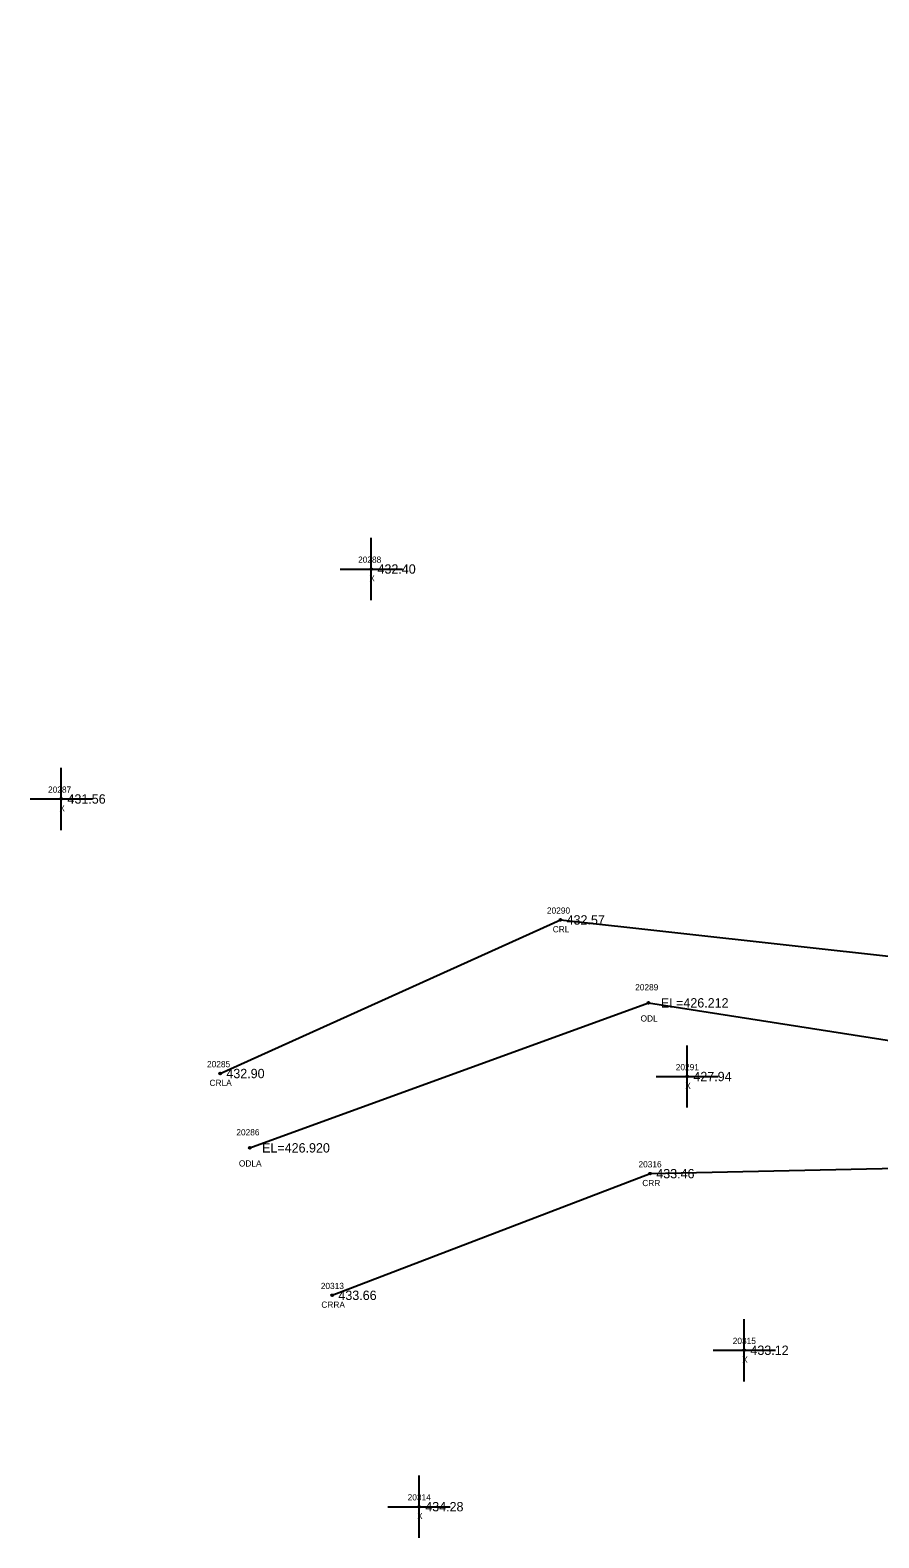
# Model space of a CAD drawing. Extents: x 1755707 to 1756750, y 975854 to 977363.
# Drawn here: x 1755706.8 to 1755843.1, y 976366.1 to 976608 of the extents above; entities that cross this region are included whole.
import ezdxf

# ---------------------------------------------------------------- set-up
doc = ezdxf.new("R2010")
doc.units = 0
for name, color, linetype in [('RD_EX_H2O', 7, 'Continuous'), ('RD_EX_H2O_txCode', 7, 'Continuous'), ('RD_EX_Misc', 7, 'Continuous'), ('RD_EX_Misc_txCode', 7, 'Continuous'), ('RD_EX_TX_H2O_ELEV', 7, 'Continuous'), ('RD_EX_TX_Misc_ELEV', 7, 'Continuous'), ('RD_SMD_Locator', 7, 'Continuous')]:
    doc.layers.add(name, color=color, linetype=linetype)

msp = doc.modelspace()

# ---------------------------------------------------------------- linework, layer by layer
at = {"layer": 'RD_EX_H2O'}
for points in [[(1755737.32, 976440.59), (1755791.96, 976465.24), (1755883.28, 976455.13), (1755971.27, 976482.19), (1756023.59, 976552.72), (1756109.16, 976576.08), (1756159.34, 976597.67), (1756188.28, 976619.95), (1756188.72, 976628.61)], [(1755742.06, 976428.66), (1755806.09, 976451.93), (1755887.6, 976439.2), (1755982.53, 976463.01), (1756033.69, 976542.66), (1756128.83, 976549.6), (1756169.54, 976582.49), (1756188.08, 976603.54), (1756206.03, 976613.84), (1756222.85, 976613.36), (1756242.15, 976615.93), (1756317.48, 976609.64), (1756394.89, 976590.11), (1756422.33, 976593.66), (1756518.23, 976582.93), (1756609.24, 976524.24), (1756704.51, 976490.62)], [(1755755.31, 976405), (1755806.36, 976424.52), (1755883.37, 976426.21), (1755989.26, 976449.51), (1756040.99, 976524.41), (1756109.22, 976532.55), (1756144.58, 976545.85), (1756166.57, 976563.07), (1756180.02, 976571), (1756216.66, 976584.76), (1756224.04, 976598.1), (1756313.82, 976585.45), (1756418.42, 976576.49), (1756511.71, 976558.86), (1756604.42, 976511.73), (1756702.67, 976481.09)]]:
    msp.add_lwpolyline(points, dxfattribs=at)
at = {"layer": 'RD_EX_Misc'}
for p, q in [((1755761.59, 976516.55), (1755761.59, 976526.55)), ((1755756.59, 976521.55), (1755766.59, 976521.55)), ((1755711.8, 976479.65), (1755711.8, 976489.65)), ((1755706.8, 976484.65), (1755716.8, 976484.65)), ((1755812.32, 976435.11), (1755812.32, 976445.11)), ((1755807.32, 976440.11), (1755817.32, 976440.11)), ((1755821.48, 976391.18), (1755821.48, 976401.18)), ((1755816.48, 976396.18), (1755826.48, 976396.18)), ((1755769.26, 976366.08), (1755769.26, 976376.08)), ((1755764.26, 976371.08), (1755774.26, 976371.08))]:
    msp.add_line(p, q, dxfattribs=at)
at = {"layer": 'RD_SMD_Locator'}
for centre in [(1755761.59, 976521.55), (1755711.8, 976484.65), (1755791.96, 976465.24), (1755806.09, 976451.93), (1755737.32, 976440.59), (1755812.32, 976440.11), (1755742.06, 976428.66), (1755806.36, 976424.52), (1755755.31, 976405), (1755821.48, 976396.18), (1755769.26, 976371.08)]:
    msp.add_circle(centre, 0.15, dxfattribs=at)

# ---------------------------------------------------------------- texts
at = {"layer": 'RD_EX_H2O_txCode'}
for s, p in [('20290', (1755789.8, 976466.24)), ('CRL', (1755790.73, 976463.24)), ('20289', (1755803.97, 976453.93)), ('ODL', (1755804.84, 976448.93)), ('20285', (1755735.21, 976441.59)), ('CRLA', (1755735.61, 976438.59)), ('20286', (1755739.92, 976430.66)), ('ODLA', (1755740.33, 976425.66)), ('20316', (1755804.5, 976425.52)), ('CRR', (1755805.11, 976422.52)), ('20313', (1755753.48, 976406)), ('CRRA', (1755753.57, 976403))]:
    msp.add_text(s, height=1, dxfattribs=at).set_placement(p)
at = {"layer": 'RD_EX_Misc_txCode'}
for s, p in [('20288', (1755759.47, 976522.55)), ('X', (1755761.27, 976519.55)), ('20287', (1755709.68, 976485.65)), ('X', (1755711.49, 976482.65)), ('20291', (1755810.49, 976441.11)), ('X', (1755812.01, 976438.11)), ('20315', (1755819.64, 976397.18)), ('X', (1755821.16, 976394.18)), ('20314', (1755767.43, 976372.08)), ('X', (1755768.95, 976369.08))]:
    msp.add_text(s, height=1, dxfattribs=at).set_placement(p)
at = {"layer": 'RD_EX_TX_H2O_ELEV'}
for s, p in [('432.57', (1755792.96, 976464.49)), ('EL=426.212', (1755808.09, 976451.18)), ('432.90', (1755738.32, 976439.84)), ('EL=426.920', (1755744.06, 976427.91)), ('433.46', (1755807.36, 976423.77)), ('433.66', (1755756.31, 976404.25))]:
    msp.add_text(s, height=1.5, dxfattribs=at).set_placement(p)
at = {"layer": 'RD_EX_TX_Misc_ELEV'}
for s, p in [('432.40', (1755762.59, 976520.8)), ('431.56', (1755712.8, 976483.9)), ('427.94', (1755813.32, 976439.36)), ('433.12', (1755822.48, 976395.43)), ('434.28', (1755770.26, 976370.33))]:
    msp.add_text(s, height=1.5, dxfattribs=at).set_placement(p)

doc.saveas('drawing.dxf')
